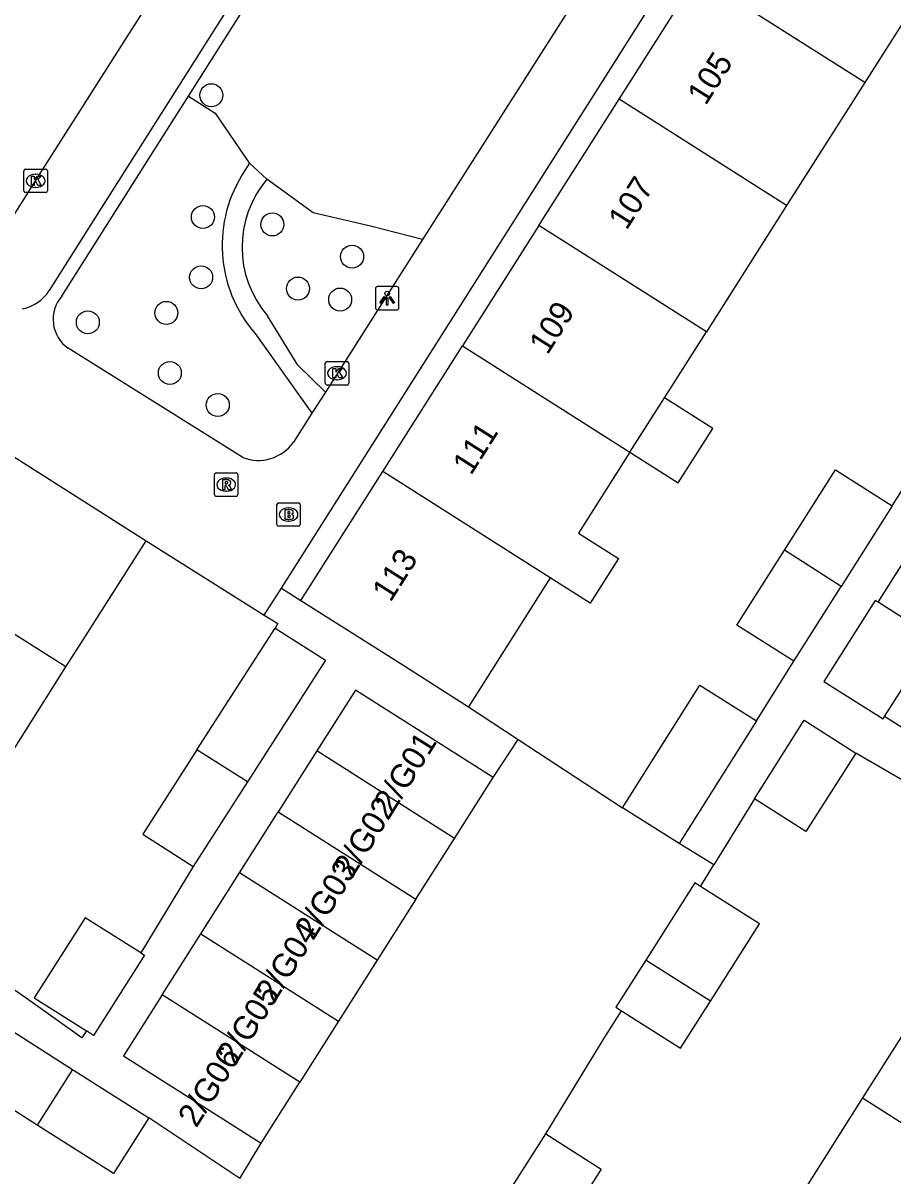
# Model space of a CAD drawing. Extents: x 159040 to 160094, y 381214 to 382518.
# Drawn here: x 159341.77 to 159378.8, y 381797.34 to 381846.41 of the extents above; entities that cross this region are included whole.
import ezdxf

# ---------------------------------------------------------------- set-up
doc = ezdxf.new("R2010")
doc.units = 0
for name, color, linetype in [('IMGEO_Boom', 7, 'Continuous'), ('IMGEO_Brandkraan', 7, 'Continuous'), ('IMGEO_Groenvoorziening', 7, 'Continuous'), ('IMGEO_Kolk', 7, 'Continuous'), ('IMGEO_Lichtpunt', 7, 'Continuous'), ('IMGEO_Muur', 7, 'Continuous'), ('IMGEO_Pand', 7, 'Continuous'), ('IMGEO_Pand_nummerreeks', 7, 'Continuous'), ('IMGEO_Rijbaan_lokaal_open', 7, 'Continuous'), ('IMGEO_Rioolput', 7, 'Continuous'), ('IMGEO_Voetpad_halfverhard', 7, 'Continuous'), ('IMGEO_Voetpad_open', 7, 'Continuous')]:
    doc.layers.add(name, color=color, linetype=linetype)

msp = doc.modelspace()

# ---------------------------------------------------------------- linework, layer by layer
at = {"layer": 'IMGEO_Boom'}
for centre in [(159349.785, 381843.344), (159349.428, 381838.159), (159352.386, 381837.843), (159355.779, 381836.473), (159349.353, 381835.594), (159353.474, 381835.114), (159355.27, 381834.645), (159347.872, 381834.079), (159344.53, 381833.678), (159348.02, 381831.521), (159350.06, 381830.158)]:
    msp.add_circle(centre, 0.489, dxfattribs=at)
at = {"layer": 'IMGEO_Brandkraan'}
for p, q in [((159352.573, 381825.068), (159352.573, 381825.92)), ((159352.648, 381825.994), (159353.5, 381825.994)), ((159353.574, 381825.92), (159353.574, 381825.068)), ((159353.061, 381825.774), (159353.086, 381825.774)), ((159353.5, 381824.994), (159352.648, 381824.994)), ((159353.084, 381825.214), (159353.059, 381825.214))]:
    msp.add_line(p, q, dxfattribs=at)
for points in [[(159352.573, 381825.068), (159352.573, 381825.92)], [(159352.648, 381825.994), (159353.5, 381825.994)], [(159353.574, 381825.92), (159353.574, 381825.068)], [(159352.921, 381825.694), (159352.921, 381825.294), (159353.134, 381825.294)], [(159353.152, 381825.694), (159352.921, 381825.694)], [(159353.1, 381825.613), (159353.046, 381825.613), (159353.046, 381825.537)], [(159353.046, 381825.537), (159353.099, 381825.537)], [(159353.108, 381825.461), (159353.046, 381825.461), (159353.046, 381825.38)], [(159353.046, 381825.38), (159353.108, 381825.38)], [(159353.5, 381824.994), (159352.648, 381824.994)]]:
    msp.add_lwpolyline(points, dxfattribs=at)
for centre, radius, start, end in [((159352.65, 381825.918), 0.0765, 91.552, 178.448), ((159352.65, 381825.918), 0.0765, 91.552, 178.448), ((159353.498, 381825.918), 0.0765, 1.552, 88.448), ((159353.498, 381825.918), 0.0765, 1.552, 88.448), ((159353.101, 381825.575), 0.0379, 267.8285, 90.9355), ((159353.109, 381825.42), 0.0404, 269.8759, 90.5077), ((159353.156, 381825.549), 0.145, 59.4692, 91.5367), ((159353.181, 381825.596), 0.0922, 285.5137, 58.1501), ((159353.186, 381825.404), 0.105, 301.3115, 78.989), ((159352.65, 381825.07), 0.0765, 181.552, 268.448), ((159352.65, 381825.07), 0.0765, 181.552, 268.448), ((159353.14, 381825.545), 0.251, 268.6676, 293.5347), ((159353.498, 381825.07), 0.0765, 271.552, 358.448), ((159353.498, 381825.07), 0.0765, 271.552, 358.448)]:
    msp.add_arc(centre, radius, start, end, dxfattribs=at)
for centre, major_axis, ratio, start_param, end_param in [((159353.06, 381825.494), (-0.387, 0.002), 0.722429, 4.712389, 7.853982), ((159353.085, 381825.494), (-0.39, 0.002), 0.717154, 1.570796, 4.712389)]:
    msp.add_ellipse(centre, major_axis=major_axis, ratio=ratio, start_param=start_param, end_param=end_param, dxfattribs=at)
at = {"layer": 'IMGEO_Groenvoorziening'}
for points in [[(159348.816, 381843.306), (159349.956, 381842.576), (159351.386, 381840.481), (159351.417, 381840.452)], [(159358.779, 381837.209), (159356.566, 381837.77), (159354.123, 381838.332), (159352.153, 381839.772)]]:
    msp.add_lwpolyline(points, dxfattribs=at)
at = {"layer": 'IMGEO_Kolk'}
for p, q in [((159341.806, 381839.274), (159341.806, 381840.126)), ((159341.881, 381840.2), (159342.733, 381840.2)), ((159342.807, 381840.126), (159342.807, 381839.274)), ((159342.294, 381839.98), (159342.319, 381839.98)), ((159342.733, 381839.2), (159341.881, 381839.2)), ((159342.317, 381839.42), (159342.292, 381839.42)), ((159354.635, 381831.082), (159354.635, 381831.934)), ((159354.71, 381832.008), (159355.562, 381832.008)), ((159355.123, 381831.788), (159355.148, 381831.788)), ((159355.636, 381831.934), (159355.636, 381831.082)), ((159355.562, 381831.008), (159354.71, 381831.008)), ((159355.146, 381831.228), (159355.121, 381831.228))]:
    msp.add_line(p, q, dxfattribs=at)
for points in [[(159341.806, 381839.274), (159341.806, 381840.126)], [(159341.881, 381840.2), (159342.733, 381840.2)], [(159342.807, 381840.126), (159342.807, 381839.274)], [(159342.127, 381839.9), (159342.25, 381839.9), (159342.25, 381839.749), (159342.38, 381839.9), (159342.544, 381839.9), (159342.398, 381839.749), (159342.551, 381839.5), (159342.399, 381839.5), (159342.314, 381839.664), (159342.25, 381839.597), (159342.25, 381839.5), (159342.127, 381839.5), (159342.127, 381839.9)], [(159342.733, 381839.2), (159341.881, 381839.2)], [(159354.635, 381831.082), (159354.635, 381831.934)], [(159354.71, 381832.008), (159355.562, 381832.008)], [(159355.636, 381831.934), (159355.636, 381831.082)], [(159354.956, 381831.708), (159355.079, 381831.708), (159355.079, 381831.557), (159355.209, 381831.708), (159355.373, 381831.708), (159355.227, 381831.557), (159355.38, 381831.308), (159355.228, 381831.308), (159355.143, 381831.472), (159355.079, 381831.405), (159355.079, 381831.308), (159354.956, 381831.308), (159354.956, 381831.708)], [(159355.562, 381831.008), (159354.71, 381831.008)]]:
    msp.add_lwpolyline(points, dxfattribs=at)
for centre, start, end in [((159341.883, 381840.124), 91.552, 178.448), ((159341.883, 381840.124), 91.552, 178.448), ((159342.731, 381840.124), 1.552, 88.448), ((159342.731, 381840.124), 1.552, 88.448), ((159341.883, 381839.276), 181.552, 268.448), ((159341.883, 381839.276), 181.552, 268.448), ((159342.731, 381839.276), 271.552, 358.448), ((159342.731, 381839.276), 271.552, 358.448), ((159354.712, 381831.932), 91.552, 178.448), ((159354.712, 381831.932), 91.552, 178.448), ((159355.56, 381831.932), 1.552, 88.448), ((159355.56, 381831.932), 1.552, 88.448), ((159354.712, 381831.084), 181.552, 268.448), ((159354.712, 381831.084), 181.552, 268.448), ((159355.56, 381831.084), 271.552, 358.448), ((159355.56, 381831.084), 271.552, 358.448)]:
    msp.add_arc(centre, 0.0765, start, end, dxfattribs=at)
for centre, major_axis, ratio, start_param, end_param in [((159342.293, 381839.7), (-0.387, 0.002), 0.722429, 4.712389, 7.853982), ((159342.318, 381839.7), (-0.39, 0.002), 0.717154, 1.570796, 4.712389), ((159355.122, 381831.508), (-0.387, 0.002), 0.722429, 4.712389, 7.853982), ((159355.147, 381831.508), (-0.39, 0.002), 0.717154, 1.570796, 4.712389)]:
    msp.add_ellipse(centre, major_axis=major_axis, ratio=ratio, start_param=start_param, end_param=end_param, dxfattribs=at)
at = {"layer": 'IMGEO_Lichtpunt'}
for p, q in [((159357.674, 381835.201), (159356.866, 381835.201)), ((159357.674, 381835.201), (159356.866, 381835.201)), ((159356.772, 381835.106), (159356.772, 381834.299)), ((159356.772, 381835.106), (159356.772, 381834.299)), ((159357.768, 381834.299), (159357.768, 381835.106)), ((159357.768, 381834.299), (159357.768, 381835.106)), ((159356.866, 381834.205), (159357.674, 381834.205)), ((159356.866, 381834.205), (159357.674, 381834.205))]:
    msp.add_line(p, q, dxfattribs=at)
for points in [[(159357.146, 381834.77), (159357.185, 381834.742), (159356.997, 381834.48), (159356.959, 381834.507), (159357.146, 381834.77)], [(159357.248, 381834.722), (159357.295, 381834.722), (159357.295, 381834.4), (159357.248, 381834.4), (159357.248, 381834.722)], [(159357.358, 381834.742), (159357.396, 381834.769), (159357.583, 381834.507), (159357.544, 381834.479), (159357.358, 381834.742)]]:
    msp.add_lwpolyline(points, dxfattribs=at)
msp.add_circle((159357.271, 381834.904), 0.0994, dxfattribs=at)
for centre, start, end in [((159356.866, 381835.106), 90, 180), ((159356.866, 381835.106), 90, 180), ((159357.674, 381835.106), 0, 90), ((159357.674, 381835.106), 0, 90), ((159356.866, 381834.299), 180, 270), ((159356.866, 381834.299), 180, 270), ((159357.674, 381834.299), 270, 0), ((159357.674, 381834.299), 270, 360)]:
    msp.add_arc(centre, 0.0946, start, end, dxfattribs=at)
at = {"layer": 'IMGEO_Muur'}
msp.add_lwpolyline([(159347.007, 381824.38), (159352.041, 381821.217)], dxfattribs=at)
at = {"layer": 'IMGEO_Pand'}
for points in [[(159380.886, 381849.076), (159377.596, 381843.891)], [(159367.14, 381843.178), (159370.464, 381848.417)], [(159377.596, 381843.891), (159370.464, 381848.417)], [(159377.596, 381843.891), (159374.271, 381838.652)], [(159363.729, 381837.804), (159367.14, 381843.178)], [(159374.271, 381838.652), (159367.14, 381843.178)], [(159374.271, 381838.652), (159370.86, 381833.278)], [(159363.729, 381837.804), (159360.473, 381832.674)], [(159370.86, 381833.278), (159363.729, 381837.804)], [(159369.074, 381830.464), (159370.86, 381833.278)], [(159357.08, 381827.327), (159360.473, 381832.674)], [(159360.473, 381832.674), (159367.604, 381828.148)], [(159367.604, 381828.148), (159369.074, 381830.464)], [(159367.604, 381828.148), (159369.661, 381826.842), (159371.131, 381829.158), (159369.074, 381830.464)], [(159340.106, 381828.76), (159347.007, 381824.38)], [(159367.604, 381828.148), (159365.414, 381824.697), (159367.114, 381823.618), (159365.91, 381821.722), (159364.211, 381822.801)], [(159353.599, 381821.842), (159357.08, 381827.327)], [(159364.211, 381822.801), (159357.08, 381827.327)], [(159374.18, 381823.974), (159376.352, 381827.396), (159378.771, 381825.861)], [(159378.771, 381825.861), (159376.6, 381822.439)], [(159343.598, 381819.009), (159344.328, 381820.159), (159347.007, 381824.38)], [(159374.577, 381819.251), (159372.157, 381820.787), (159374.18, 381823.974)], [(159376.6, 381822.439), (159374.18, 381823.974)], [(159343.598, 381819.009), (159336.698, 381823.375)], [(159364.211, 381822.801), (159360.73, 381817.316)], [(159374.577, 381819.251), (159376.6, 381822.439)], [(159353.599, 381821.842), (159357.821, 381819.163), (159360.73, 381817.316)], [(159378.163, 381821.763), (159378.04, 381821.841), (159375.853, 381818.394), (159378.377, 381816.793), (159378.44, 381816.892)], [(159378.44, 381816.892), (159380.564, 381820.24), (159378.163, 381821.763)], [(159349.175, 381815.48), (159352.497, 381820.664)], [(159352.497, 381820.664), (159354.641, 381819.29), (159351.327, 381814.119)], [(159340.197, 381813.649), (159343.598, 381819.009)], [(159361.787, 381814.307), (159355.927, 381818.026), (159354.28, 381815.431)], [(159367.287, 381813.012), (159370.575, 381818.233), (159372.987, 381816.714)], [(159372.987, 381816.714), (159369.699, 381811.493)], [(159372.909, 381813.395), (159375.014, 381816.746), (159377.22, 381815.334)], [(159349.175, 381815.48), (159346.876, 381811.893), (159349.02, 381810.519)], [(159351.327, 381814.119), (159349.175, 381815.48)], [(159354.28, 381815.431), (159352.634, 381812.836)], [(159360.14, 381811.712), (159354.28, 381815.431)], [(159377.22, 381815.334), (159375.087, 381812.001), (159372.909, 381813.395)], [(159351.327, 381814.119), (159349.02, 381810.519)], [(159360.14, 381811.712), (159361.787, 381814.307)], [(159350.987, 381810.241), (159352.634, 381812.836)], [(159352.634, 381812.836), (159358.493, 381809.117)], [(159369.699, 381811.493), (159367.287, 381813.012)], [(159358.493, 381809.117), (159360.14, 381811.712)], [(159349.34, 381807.646), (159350.987, 381810.241)], [(159356.846, 381806.522), (159350.987, 381810.241)], [(159370.609, 381809.668), (159370.372, 381809.818), (159368.279, 381806.521)], [(159371.028, 381804.776), (159373.121, 381808.073), (159370.609, 381809.668)], [(159358.493, 381809.117), (159356.846, 381806.522)], [(159346.78, 381806.836), (159344.416, 381808.336), (159342.253, 381804.927), (159344.476, 381803.517)], [(159347.693, 381805.052), (159349.34, 381807.646)], [(159349.34, 381807.646), (159355.2, 381803.928)], [(159346.78, 381806.836), (159346.936, 381806.737), (159344.773, 381803.328), (159344.476, 381803.517)], [(159356.846, 381806.522), (159355.2, 381803.928)], [(159368.279, 381806.521), (159367.009, 381804.521), (159367.246, 381804.371)], [(159371.028, 381804.776), (159370.872, 381804.875), (159368.516, 381806.371), (159368.279, 381806.521)], [(159380.824, 381805.889), (159377.508, 381800.663)], [(159347.693, 381805.052), (159346.047, 381802.457), (159351.906, 381798.738)], [(159353.553, 381801.333), (159347.693, 381805.052)], [(159367.246, 381804.371), (159369.758, 381802.776), (159371.028, 381804.776)], [(159342.376, 381799.511), (159338.97, 381801.672), (159340.472, 381804.038)], [(159340.472, 381804.038), (159343.878, 381801.877)], [(159355.2, 381803.928), (159353.553, 381801.333)], [(159343.878, 381801.877), (159342.376, 381799.511)], [(159343.878, 381801.877), (159347.126, 381799.816)], [(159351.906, 381798.738), (159353.553, 381801.333)], [(159377.508, 381800.663), (159374.163, 381795.393)], [(159377.508, 381800.663), (159384.599, 381796.162)], [(159347.126, 381799.816), (159345.624, 381797.45), (159342.376, 381799.511)], [(159361.913, 381795.81), (159364.02, 381799.13)], [(159364.02, 381799.13), (159366.376, 381797.635), (159364.269, 381794.314)]]:
    msp.add_lwpolyline(points, dxfattribs=at)
at = {"layer": 'IMGEO_Rijbaan_lokaal_open'}
for points in [[(159338.189, 381833.159), (159342.307, 381839.702), (159347.915, 381848.544), (159353.758, 381857.696), (159361.37, 381869.614), (159365.312, 381875.921), (159366.451, 381877.655)], [(159361.787, 381814.307), (159362.849, 381815.925)], [(159362.849, 381815.925), (159367.287, 381813.012)], [(159371.173, 381810.583), (159369.699, 381811.493)], [(159370.609, 381809.668), (159371.173, 381810.583)], [(159364.02, 381799.13), (159366.463, 381803.137), (159367.246, 381804.371)], [(159350.999, 381797.237), (159351.906, 381798.738)]]:
    msp.add_lwpolyline(points, dxfattribs=at)
at = {"layer": 'IMGEO_Rioolput'}
for p, q in [((159349.919, 381826.342), (159349.919, 381827.194)), ((159349.994, 381827.268), (159350.846, 381827.268)), ((159350.407, 381827.048), (159350.432, 381827.048)), ((159350.92, 381827.194), (159350.92, 381826.342)), ((159350.43, 381826.488), (159350.405, 381826.488)), ((159350.846, 381826.268), (159349.994, 381826.268))]:
    msp.add_line(p, q, dxfattribs=at)
for points in [[(159349.919, 381826.342), (159349.919, 381827.194)], [(159349.994, 381827.268), (159350.846, 381827.268)], [(159350.508, 381826.966), (159350.256, 381826.968), (159350.256, 381826.568)], [(159350.434, 381826.887), (159350.38, 381826.887), (159350.38, 381826.806)], [(159350.92, 381827.194), (159350.92, 381826.342)], [(159350.256, 381826.568), (159350.38, 381826.568), (159350.38, 381826.73), (159350.391, 381826.73)], [(159350.38, 381826.806), (159350.432, 381826.806)], [(159350.438, 381826.701), (159350.509, 381826.568), (159350.649, 381826.568), (159350.584, 381826.694)], [(159350.846, 381826.268), (159349.994, 381826.268)]]:
    msp.add_lwpolyline(points, dxfattribs=at)
for centre, radius, start, end in [((159349.996, 381827.192), 0.0765, 91.552, 178.448), ((159349.996, 381827.192), 0.0765, 91.552, 178.448), ((159350.44, 381826.791), 0.0964, 77.0061, 93.1865), ((159350.454, 381826.848), 0.0378, 276.6634, 79.6772), ((159350.507, 381826.856), 0.109, 350.3612, 89.416), ((159350.505, 381826.856), 0.112, 277.5842, 350.9817), ((159350.844, 381827.192), 0.0765, 1.552, 88.448), ((159350.844, 381827.192), 0.0765, 1.552, 88.448), ((159349.996, 381826.344), 0.0765, 181.552, 268.448), ((159349.996, 381826.344), 0.0765, 181.552, 268.448), ((159350.39, 381826.677), 0.0533, 26.0293, 88.6989), ((159350.416, 381826.995), 0.19, 274.7715, 282.9687), ((159350.489, 381826.641), 0.108, 29.5134, 73.7905), ((159350.844, 381826.344), 0.0765, 271.552, 358.448), ((159350.844, 381826.344), 0.0765, 271.552, 358.448)]:
    msp.add_arc(centre, radius, start, end, dxfattribs=at)
for centre, major_axis, ratio, start_param, end_param in [((159350.406, 381826.768), (-0.387, 0.002), 0.722429, 4.712389, 7.853982), ((159350.431, 381826.768), (-0.39, 0.002), 0.717154, 1.570796, 4.712389)]:
    msp.add_ellipse(centre, major_axis=major_axis, ratio=ratio, start_param=start_param, end_param=end_param, dxfattribs=at)
at = {"layer": 'IMGEO_Voetpad_halfverhard'}
for points in [[(159351.417, 381840.452), (159351.218, 381840.142)], [(159352.153, 381839.772), (159351.417, 381840.452)], [(159354.639, 381830.704), (159353.462, 381831.85), (159352.173, 381833.956)], [(159351.654, 381833.201), (159354.068, 381829.807)]]:
    msp.add_lwpolyline(points, dxfattribs=at)
for centre, radius, start, end in [((159355.955, 381836.955), 5.709, 146.0731, 221.1155), ((159355.578, 381836.876), 4.485, 139.7817, 220.6124)]:
    msp.add_arc(centre, radius, start, end, dxfattribs=at)
at = {"layer": 'IMGEO_Voetpad_open'}
for points in [[(159352.77, 381822.367), (159385.148, 381873.477)], [(159366.807, 381872.694), (159363.887, 381868.023), (159350.427, 381846.945), (159344.824, 381838.112), (159342.881, 381835.025)], [(159348.816, 381843.306), (159356.8, 381855.922), (159357.599, 381857.253)], [(159367.032, 381850.318), (159366.269, 381848.977), (159358.779, 381837.209)], [(159343.419, 381834.788), (159348.023, 381842.053), (159348.816, 381843.306)], [(159358.779, 381837.209), (159354.639, 381830.704)], [(159351.121, 381827.924), (159343.692, 381832.573)], [(159354.639, 381830.704), (159354.068, 381829.807)], [(159354.068, 381829.807), (159353.284, 381828.575)], [(159378.771, 381825.861), (159381.244, 381829.755)], [(159378.163, 381821.763), (159380.666, 381825.707)], [(159347.007, 381824.38), (159352.041, 381821.217)], [(159352.041, 381821.217), (159352.77, 381822.367)], [(159352.77, 381822.367), (159353.599, 381821.842)], [(159352.041, 381821.217), (159352.619, 381820.854), (159352.497, 381820.664)], [(159372.987, 381816.714), (159374.577, 381819.251)], [(159360.73, 381817.316), (159362.849, 381815.925)], [(159385.104, 381812.662), (159378.44, 381816.892)], [(159384.239, 381811.27), (159377.22, 381815.334)], [(159372.909, 381813.395), (159371.173, 381810.583)], [(159349.02, 381810.519), (159346.78, 381806.836)], [(159344.476, 381803.517), (159344.27, 381803.226), (159341.9, 381804.904), (159336.865, 381808.398)], [(159350.999, 381797.237), (159347.126, 381799.816)]]:
    msp.add_lwpolyline(points, dxfattribs=at)
for centre, radius, start, end in [((159341.442, 381835.929), 1.7, 280.1, 327.8576), ((159344.552, 381833.803), 1.501, 138.9944, 235.0582), ((159351.784, 381829.638), 1.838, 248.8427, 324.6578)]:
    msp.add_arc(centre, radius, start, end, dxfattribs=at)

# ---------------------------------------------------------------- texts
at = {"layer": 'IMGEO_Pand_nummerreeks'}
for s, rotation, p in [('105', 57.599, (159370.827, 381842.867)), ('107', 57.599, (159367.46, 381837.562)), ('109', 57.5994, (159364.094, 381832.257)), ('111', 57.599, (159360.838, 381827.127)), ('113', 57.599, (159357.412, 381821.728)), ('2/G01', 58.0552, (159357.489, 381812.73)), ('2/G02', 58.0552, (159355.771, 381809.975)), ('2/G03', 58.0552, (159354.119, 381807.324)), ('2/G04', 58.0552, (159352.462, 381804.668)), ('2/G05', 58.0552, (159350.806, 381802.011)), ('2/G06', 58.0552, (159349.15, 381799.355))]:
    msp.add_text(s, height=1, rotation=rotation, dxfattribs=at).set_placement(p)

doc.saveas('drawing.dxf')
